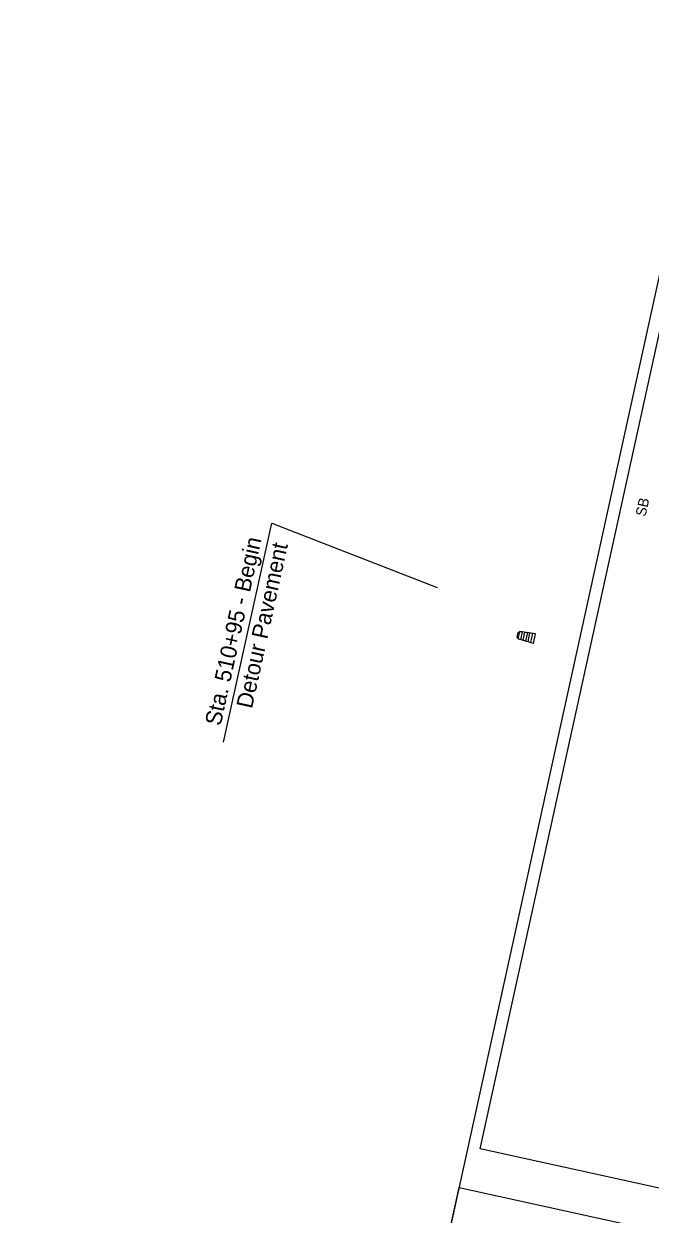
# Model space of a CAD drawing. Extents: x 14104283 to 14121738, y 8635219 to 8671666.
# Drawn here: x 14106925 to 14107409, y 8638817 to 8639736 of the extents above; entities that cross this region are included whole.
import ezdxf

# ---------------------------------------------------------------- set-up
doc = ezdxf.new("R2010")
doc.units = 0
for name, color, linetype in [('Cell', 7, 'Continuous'), ('dsnNonPlotable', 7, 'Continuous'), ('dsnTextFinalPlan', 7, 'Continuous'), ('dsnTextOverlapEven', 7, 'Continuous'), ('dsnTextOverlapOdd', 7, 'Continuous'), ('Level 2', 7, 'Continuous')]:
    doc.layers.add(name, color=color, linetype=linetype)

msp = doc.modelspace()

# ---------------------------------------------------------------- linework, layer by layer
at = {"layer": 'Cell'}
for p, q in [((14107305.99, 8639262.24), (14107306.85, 8639266.14)), ((14107305.99, 8639262.24), (14107306.75, 8639261.05)), ((14107318.62, 8639257.58), (14107306.75, 8639261.05)), ((14107306.85, 8639266.14), (14107308.04, 8639266.91)), ((14107320.27, 8639265.07), (14107308.04, 8639266.91)), ((14107318.62, 8639257.58), (14107320.27, 8639265.07))]:
    msp.add_line(p, q, dxfattribs=at)
for points in [[(14107306.75, 8639261.05), (14107308.04, 8639266.91), (14107310.02, 8639266.61), (14107308.68, 8639260.48)], [(14107310.6, 8639259.92), (14107312.01, 8639266.31), (14107313.99, 8639266.01), (14107312.53, 8639259.36)], [(14107314.45, 8639258.8), (14107315.97, 8639265.72), (14107317.95, 8639265.42), (14107316.38, 8639258.24)]]:
    msp.add_lwpolyline(points, close=True, dxfattribs=at)
at = {"layer": 'dsnNonPlotable'}
for points in [[(14107218.44, 8638642.33), (14107554.83, 8640173.31), (14108541.3, 8639956.56), (14108204.91, 8638425.58)], [(14106924.98, 8637306.69), (14107261.36, 8638837.67), (14108247.83, 8638620.92), (14107911.44, 8637089.94)]]:
    msp.add_lwpolyline(points, close=True, dxfattribs=at)
at = {"layer": 'dsnTextFinalPlan'}
msp.add_lwpolyline([(14107277.52, 8638867.57), (14107491.18, 8639840), (14107687.99, 8639796.76), (14107474.33, 8638824.33)], close=True, dxfattribs=at)
at = {"layer": 'dsnTextOverlapEven'}
msp.add_lwpolyline([(14107277.52, 8638867.57), (14107491.18, 8639840), (14107687.99, 8639796.76), (14107474.33, 8638824.33)], close=True, dxfattribs=at)
at = {"layer": 'dsnTextOverlapOdd'}
msp.add_lwpolyline([(14107079.3, 8639181.26), (14107116.47, 8639350.46), (14107244.4, 8639300.69)], dxfattribs=at)

# ---------------------------------------------------------------- texts
at = {"layer": 'dsnTextFinalPlan'}
msp.add_text('SB', height=8, rotation=77.60777, dxfattribs=at).set_placement((14107405.17, 8639355.11))
at = {"layer": 'Level 2'}
for s, p in [('Sta. 510+95 - Begin', (14107076.97, 8639193.43)), ('Detour Pavement', (14107101.21, 8639206.74))]:
    msp.add_text(s, height=12.5, rotation=77.63284, dxfattribs=at).set_placement(p)

doc.saveas('drawing.dxf')
